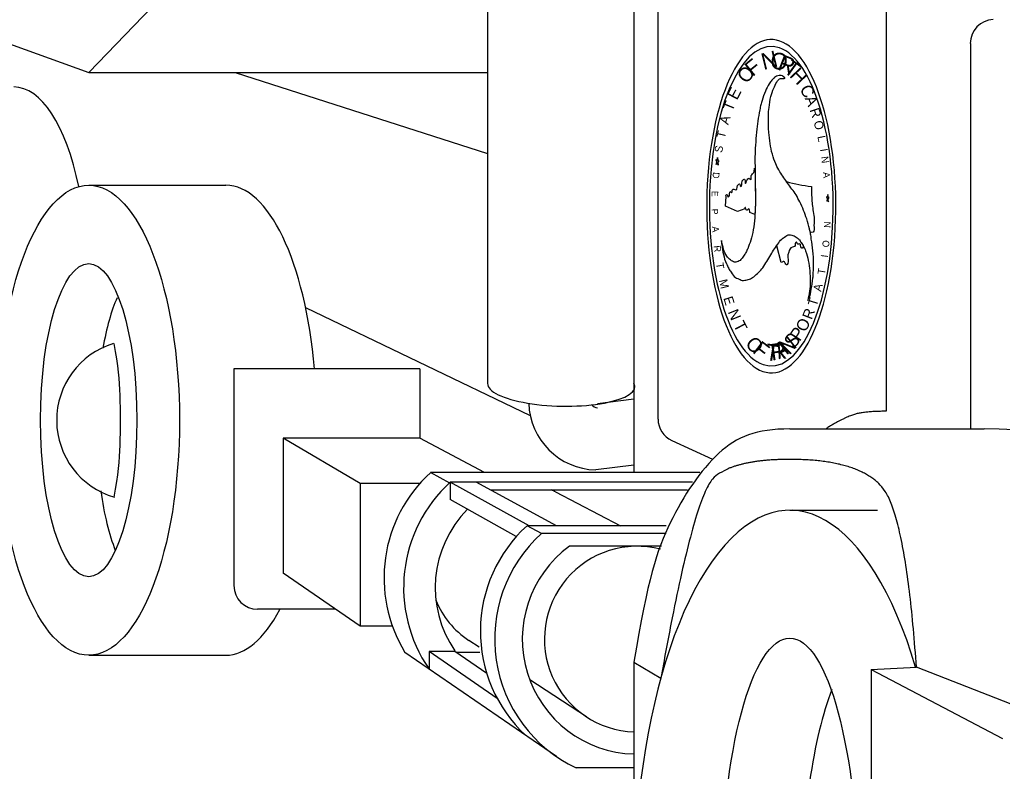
# Model space of a CAD drawing. Extents: x 2141134 to 2191774, y 803576 to 836576.
# Drawn here: x 2150196 to 2150916, y 806166 to 806717 of the extents above; entities that cross this region are included whole.
import ezdxf

# ---------------------------------------------------------------- set-up
doc = ezdxf.new("R2010")
doc.units = 0
doc.layers.add('Exist Road Secondary Type 20 SR Number Label', color=7, linetype='Continuous')

msp = doc.modelspace()

# ---------------------------------------------------------------- linework, layer by layer
at = {"layer": 'Exist Road Secondary Type 20 SR Number Label'}
for p, q in [((2150246.63, 806678.14), (2150510.12, 806951.17)), ((2150538.92, 806898.09), (2150538.92, 806450.48)), ((2150050.42, 806749.28), (2150246.63, 806678.14)), ((2150646.15, 806734.75), (2150646.15, 806385.23)), ((2150663.82, 806424.37), (2150663.82, 806736.48)), ((2150831.04, 806729.27), (2150831.04, 806430.07)), ((2150892.6, 806699.59), (2150892.6, 806417.14)), ((2150246.63, 806678.14), (2150538.92, 806678.14)), ((2150354.03, 806678.14), (2150538.92, 806618.9)), ((2150756.67, 806674.43), (2150756.58, 806674.2)), ((2150756.67, 806674.43), (2150756.58, 806674.2)), ((2150756.67, 806674.43), (2150756.58, 806674.2)), ((2150706.83, 806612.84), (2150706.24, 806614.32)), ((2150706.24, 806614.32), (2150707.07, 806614.04)), ((2150706.83, 806612.84), (2150706.24, 806614.32)), ((2150706.24, 806614.32), (2150707.07, 806614.04)), ((2150706.49, 806610.91), (2150706.83, 806612.84)), ((2150706.49, 806610.91), (2150706.83, 806612.84)), ((2150707.18, 806611.95), (2150706.49, 806610.91)), ((2150707.18, 806611.95), (2150706.49, 806610.91)), ((2150707.07, 806614.04), (2150707.39, 806615.9)), ((2150707.07, 806614.04), (2150707.39, 806615.9)), ((2150707.79, 806610.47), (2150707.18, 806611.95)), ((2150707.79, 806610.47), (2150707.18, 806611.95)), ((2150707.39, 806615.9), (2150707.57, 806613.87)), ((2150707.39, 806615.9), (2150707.57, 806613.87)), ((2150707.57, 806613.87), (2150708.37, 806613.59)), ((2150707.57, 806613.87), (2150708.37, 806613.59)), ((2150708.37, 806613.59), (2150707.64, 806612.56)), ((2150708.37, 806613.59), (2150707.64, 806612.56)), ((2150707.64, 806612.56), (2150707.79, 806610.47)), ((2150707.64, 806612.56), (2150707.79, 806610.47)), ((2150757.86, 806598.39), (2150757.86, 806598.39)), ((2150757.86, 806598.39), (2150757.86, 806598.39)), ((2150246.63, 806595.67), (2150347.17, 806595.67)), ((2150713.12, 806580.24), (2150713.59, 806587.49)), ((2150713.12, 806580.24), (2150713.59, 806587.49)), ((2150787.9, 806586.99), (2150787.1, 806587.26)), ((2150787.1, 806587.26), (2150787.7, 806585.82)), ((2150787.9, 806586.99), (2150787.1, 806587.26)), ((2150787.1, 806587.26), (2150787.7, 806585.82)), ((2150787.7, 806585.82), (2150787.36, 806583.89)), ((2150787.7, 806585.82), (2150787.36, 806583.89)), ((2150787.36, 806583.89), (2150788.05, 806584.89)), ((2150787.36, 806583.89), (2150788.05, 806584.89)), ((2150788.25, 806588.84), (2150787.9, 806586.99)), ((2150788.25, 806588.84), (2150787.9, 806586.99)), ((2150788.05, 806584.89), (2150788.64, 806583.45)), ((2150788.05, 806584.89), (2150788.64, 806583.45)), ((2150788.43, 806586.81), (2150788.25, 806588.84)), ((2150788.43, 806586.81), (2150788.25, 806588.84)), ((2150789.23, 806586.61), (2150788.43, 806586.81)), ((2150789.23, 806586.61), (2150788.43, 806586.81)), ((2150788.51, 806585.54), (2150789.23, 806586.61)), ((2150788.51, 806585.54), (2150789.23, 806586.61)), ((2150788.64, 806583.45), (2150788.51, 806585.54)), ((2150788.64, 806583.45), (2150788.51, 806585.54)), ((2150721.97, 806576.33), (2150713.12, 806580.24)), ((2150721.97, 806576.33), (2150713.12, 806580.24)), ((2150727.27, 806578.45), (2150721.97, 806576.33)), ((2150727.27, 806578.45), (2150721.97, 806576.33)), ((2150734.82, 806574.22), (2150731.12, 806575.6)), ((2150734.82, 806574.22), (2150731.12, 806575.6)), ((2150793.66, 806564.21), (2150793.66, 806564.21)), ((2150793.66, 806564.21), (2150793.66, 806564.21)), ((2150754.12, 806539.02), (2150750.75, 806551.38)), ((2150750.75, 806551.38), (2150750.75, 806551.38)), ((2150754.12, 806539.02), (2150750.75, 806551.38)), ((2150750.75, 806551.38), (2150750.75, 806551.38)), ((2150405.56, 806506.04), (2150570.09, 806427.09)), ((2150353.06, 806461.07), (2150353.06, 806302.38)), ((2150489.33, 806461.07), (2150489.33, 806410.45)), ((2150646.15, 806438.83), (2150619.33, 806435.5)), ((2150445.47, 806377.27), (2150389.03, 806410.45)), ((2150389.03, 806410.45), (2150389.03, 806311.57)), ((2150536.72, 806385.23), (2150489.33, 806410.45)), ((2150760.33, 806417.14), (2150902.72, 806417.14)), ((2150674, 806408.56), (2150703.7, 806395.06)), ((2150646.15, 806390.58), (2150618.14, 806387.1)), ((2150511.23, 806377.48), (2150497.19, 806385.23)), ((2150445.47, 806377.27), (2150445.47, 806272.58)), ((2150569.41, 806346.26), (2150511.58, 806378.13)), ((2150511.58, 806378.13), (2150511.58, 806365.43)), ((2150689, 806378.13), (2150511.58, 806378.13)), ((2150589.36, 806346.26), (2150530.52, 806378.13)), ((2150685.27, 806372.34), (2150541.21, 806372.34)), ((2150588.67, 806371), (2150636.2, 806346.26)), ((2150559.89, 806338.24), (2150511.58, 806365.43)), ((2150760.33, 806357.56), (2150824.5, 806357.56)), ((2150578.3, 806340.47), (2150567.81, 806346.26)), ((2150669.79, 806346.26), (2150567.81, 806346.26)), ((2150666.37, 806331.18), (2150598.89, 806331.18)), ((2150445.47, 806272.58), (2150389.03, 806311.57)), ((2150532.85, 806257.29), (2150525.21, 806262.25)), ((2150589.37, 806177.13), (2150478.33, 806253.46)), ((2150546, 806219.64), (2150496.02, 806254)), ((2150496.02, 806254), (2150496.02, 806241.31)), ((2150538.33, 806237.93), (2150514.96, 806254)), ((2150246.63, 806251.37), (2150347.17, 806251.37)), ((2150646.15, 806246.36), (2150665.85, 806234.58)), ((2150646.15, 806246.36), (2150646.15, 805934.23)), ((2150819.93, 806241.01), (2150853.13, 806242.62)), ((2150819.93, 806241.01), (2150819.93, 806113.39)), ((2150819.93, 806241.01), (2150916.05, 806190.3)), ((2151011.08, 806180.8), (2150853.13, 806242.62)), ((2150611.47, 806206.18), (2150569.86, 806233.23))]:
    msp.add_line(p, q, dxfattribs=at)
for points in [[(2150489.33, 806461.07), (2150353.06, 806461.07)], [(2150489.33, 806410.45), (2150389.03, 806410.45)], [(2150694.33, 806385.23), (2150497.19, 806385.23)], [(2150489.33, 806377.27), (2150445.47, 806377.27)], [(2150669.79, 806340.47), (2150578.3, 806340.47)], [(2150427.47, 806285.01), (2150370.43, 806285.01)], [(2150469.16, 806272.58), (2150445.47, 806272.58)], [(2150514.96, 806254), (2150496.02, 806254)], [(2150533.11, 806253.46), (2150515.74, 806253.46)], [(2150646.15, 806168.82), (2150603.8, 806168.82)]]:
    msp.add_lwpolyline(points, dxfattribs=at)
for centre, radius, start, end in [((2150909.96, 806699.59), 17.37, 92.07945, 180), ((2150281.92, 806423.52), 58.74, 106.95895, 253.78048), ((2150619.46, 806437.55), 50.47, 181.85685, 268.49256), ((2150619.46, 806437.55), 4.91, 212.61184, 268.49256), ((2150681.19, 806424.37), 17.37, 180, 245.54907), ((2150902.72, 806008.17), 408.97, 41.01358, 90), ((2150567.43, 806307.94), 104.43, 132.26282, 211.44584), ((2150581.82, 806300.84), 104.43, 132.26282, 214.75513), ((2150559.56, 806315.1), 63.03, 62.49925, 65.51247), ((2150581.82, 806300.84), 81.31, 135.04479, 214.75513), ((2150638.04, 806268.97), 104.43, 132.26282, 226.90002), ((2150648.53, 806263.18), 104.43, 132.26282, 244.64068), ((2150648.53, 806263.18), 84.19, 126.13067, 268.38157), ((2150648.53, 806263.18), 67.99, 75.44496, 267.99604), ((2150370.43, 806302.38), 17.37, 180, 270), ((2150559.56, 806315.1), 63.03, 201.74287, 236.97488)]:
    msp.add_arc(centre, radius, start, end, dxfattribs=at)
for centre, major_axis, ratio, start_param, end_param in [((2150746.76, 806580.28), (0, 122.07), 0.387649, 4.580113, 7.721705), ((2150746.76, 806580.28), (0, 122.07), 0.387649, 4.580113, 7.721705), ((2150746.76, 806580.28), (0, 116.98), 0.387649, 4.580113, 7.721705), ((2150746.76, 806580.28), (0, 116.98), 0.387649, 4.580113, 7.721705), ((2150191.86, 806528.25), (0, 139.42), 0.387713, 5.208857, 6.283185), ((2150785.93, 807237.89), (0, -643.58), 0.387649, 6.075485, 6.077223), ((2150785.93, 807237.89), (0, -643.58), 0.387649, 6.075485, 6.077223), ((2150785.93, 807237.89), (0, -643.58), 0.387649, 6.170414, 6.243823), ((2150785.93, 807237.89), (0, -643.58), 0.387649, 6.170414, 6.243823), ((2150347.17, 806423.52), (0, 172.15), 0.386478, 4.932222, 6.283185), ((2150746.76, 806580.28), (0, -122.06), 0.387649, 4.580113, 7.721705), ((2150746.76, 806580.28), (0, -122.06), 0.387649, 4.580113, 7.721705), ((2150746.76, 806580.28), (0, -116.98), 0.387649, 4.580113, 7.721705), ((2150746.76, 806580.28), (0, -116.98), 0.387649, 4.580113, 7.721705), ((2150287.63, 806419.18), (0, 114.7), 0.307656, 0.60872, 1.048981), ((2150592.87, 806449.26), (-53.95, 1.21), 0.285874, 6.283185, 9.588173), ((2150760.33, 806077.13), (0, 280.43), 0.407167, 5.343461, 11.004346), ((2150287.63, 806419.18), (0, 114.7), 0.307656, 1.996276, 2.486784), ((2150347.17, 806423.52), (0, 172.15), 0.386478, 3.141593, 3.775764), ((2150819.17, 806071.08), (0, -186.85), 0.26845, 3.733099, 4.225572)]:
    msp.add_ellipse(centre, major_axis=major_axis, ratio=ratio, start_param=start_param, end_param=end_param, dxfattribs=at)
for centre, major_axis, ratio in [((2150246.63, 806423.52), (0, 172.15), 0.386478), ((2150246.63, 806423.52), (0, 114.7), 0.307656), ((2150760.33, 806077.13), (0, -186.85), 0.26845)]:
    msp.add_ellipse(centre, major_axis=major_axis, ratio=ratio, dxfattribs=at)
for points in [[(2150756.58, 806674.2), (2150755.56, 806675.28), (2150752.43, 806676.03), (2150749.12, 806674.5), (2150748.82, 806674.2), (2150747.13, 806672.59), (2150745.28, 806669.94), (2150742.41, 806664.61), (2150740.07, 806657.64), (2150739.13, 806654.64), (2150738.35, 806650.82), (2150736.87, 806642.65), (2150735.9, 806634.58), (2150735.19, 806625.01), (2150734.81, 806616.52), (2150734.91, 806607.69), (2150735.04, 806598.78), (2150735.09, 806590.15), (2150735.1, 806581.28), (2150734.67, 806572.63), (2150734.62, 806571.88), (2150733.54, 806562.87), (2150731.68, 806555.3), (2150729.47, 806549.16), (2150728.21, 806546.41), (2150726.48, 806543.8), (2150725.49, 806542.27), (2150723.22, 806540.21), (2150719.91, 806539.37), (2150716.79, 806540.92), (2150714.11, 806543.7), (2150711.87, 806548.59), (2150710.23, 806555.06)], [(2150756.58, 806674.2), (2150755.56, 806675.28), (2150752.43, 806676.03), (2150749.12, 806674.5), (2150748.82, 806674.2), (2150747.13, 806672.59), (2150745.28, 806669.94), (2150742.41, 806664.61), (2150740.07, 806657.64), (2150739.13, 806654.64), (2150738.35, 806650.82), (2150736.87, 806642.65), (2150735.9, 806634.58), (2150735.19, 806625.01), (2150734.81, 806616.52), (2150734.91, 806607.69), (2150735.04, 806598.78), (2150735.09, 806590.15), (2150735.1, 806581.28), (2150734.67, 806572.63), (2150734.62, 806571.88), (2150733.54, 806562.87), (2150731.68, 806555.3), (2150729.47, 806549.16), (2150728.21, 806546.41), (2150726.48, 806543.8), (2150725.49, 806542.27), (2150723.22, 806540.21), (2150719.91, 806539.37), (2150716.79, 806540.92), (2150714.11, 806543.7), (2150711.87, 806548.59), (2150710.23, 806555.06)], [(2150773.43, 806511.15), (2150774.26, 806512.83), (2150776.1, 806519.46), (2150777.24, 806527.61), (2150777.33, 806528.42), (2150777.59, 806533.04), (2150777.63, 806538.54), (2150777.31, 806547.59), (2150776.1, 806556.25), (2150775.6, 806559.9), (2150774.68, 806563.6), (2150772.69, 806570.97), (2150770.47, 806577.17), (2150767.6, 806583.48), (2150764.93, 806588.52), (2150761.92, 806592.84), (2150758.87, 806596.95), (2150755.98, 806601.12), (2150752.94, 806605.59), (2150750.28, 806610.85), (2150750.07, 806611.4), (2150747.54, 806618.32), (2150745.94, 806626.28), (2150744.96, 806634.24), (2150744.72, 806638.38), (2150744.71, 806643.6), (2150744.65, 806646.61), (2150745.14, 806652.65), (2150746.5, 806660.54), (2150748.56, 806666.66), (2150750.85, 806671.24), (2150753.63, 806673.79), (2150756.58, 806674.2), (2150756.67, 806674.43)], [(2150773.43, 806511.15), (2150774.26, 806512.83), (2150776.1, 806519.46), (2150777.24, 806527.61), (2150777.33, 806528.42), (2150777.59, 806533.04), (2150777.63, 806538.54), (2150777.31, 806547.59), (2150776.1, 806556.25), (2150775.6, 806559.9), (2150774.68, 806563.6), (2150772.69, 806570.97), (2150770.47, 806577.17), (2150767.6, 806583.48), (2150764.93, 806588.52), (2150761.92, 806592.84), (2150758.87, 806596.95), (2150755.98, 806601.12), (2150752.94, 806605.59), (2150750.28, 806610.85), (2150750.07, 806611.4), (2150747.54, 806618.32), (2150745.94, 806626.28), (2150744.96, 806634.24), (2150744.72, 806638.38), (2150744.71, 806643.6), (2150744.65, 806646.61), (2150745.14, 806652.65), (2150746.5, 806660.54), (2150748.56, 806666.66), (2150750.85, 806671.24), (2150753.63, 806673.79), (2150756.58, 806674.2), (2150756.67, 806674.43)], [(2150713.59, 806587.49), (2150713.53, 806588.21), (2150714.04, 806588.83), (2150715.29, 806586.98), (2150716.03, 806588.22), (2150716.08, 806589.7), (2150716.69, 806590.99), (2150717.57, 806590.22), (2150718.52, 806592.62), (2150719.3, 806592.83), (2150720.88, 806592.29), (2150723.01, 806596.52), (2150723.82, 806596.54), (2150723.95, 806595.18), (2150724.42, 806594.76), (2150725.43, 806598.5), (2150725.67, 806599), (2150727.22, 806600), (2150727.58, 806599.15), (2150727.6, 806597.32), (2150727.79, 806596.89), (2150728.32, 806597.62), (2150729.08, 806599.55), (2150730.38, 806600.75), (2150731.73, 806599.84), (2150732.12, 806602.67), (2150733.87, 806604.91), (2150734.29, 806606.48), (2150734.47, 806608.18)], [(2150713.59, 806587.49), (2150713.53, 806588.21), (2150714.04, 806588.83), (2150715.29, 806586.98), (2150716.03, 806588.22), (2150716.08, 806589.7), (2150716.69, 806590.99), (2150717.57, 806590.22), (2150718.52, 806592.62), (2150719.3, 806592.83), (2150720.88, 806592.29), (2150723.01, 806596.52), (2150723.82, 806596.54), (2150723.95, 806595.18), (2150724.42, 806594.76), (2150725.43, 806598.5), (2150725.67, 806599), (2150727.22, 806600), (2150727.58, 806599.15), (2150727.6, 806597.32), (2150727.79, 806596.89), (2150728.32, 806597.62), (2150729.08, 806599.55), (2150730.38, 806600.75), (2150731.73, 806599.84), (2150732.12, 806602.67), (2150733.87, 806604.91), (2150734.29, 806606.48), (2150734.47, 806608.18)], [(2150734.9, 806607.91), (2150734.91, 806607.69), (2150735.04, 806598.78), (2150735.09, 806590.15), (2150735.1, 806581.28), (2150734.81, 806574.22)], [(2150734.9, 806607.91), (2150734.91, 806607.69), (2150735.04, 806598.78), (2150735.09, 806590.15), (2150735.1, 806581.28), (2150734.81, 806574.22)], [(2150775.31, 806561.31), (2150774.68, 806563.6), (2150772.69, 806570.97), (2150770.47, 806577.17), (2150767.6, 806583.48), (2150764.93, 806588.52), (2150761.92, 806592.84), (2150758.87, 806596.95), (2150757.86, 806598.39)], [(2150775.31, 806561.31), (2150774.68, 806563.6), (2150772.69, 806570.97), (2150770.47, 806577.17), (2150767.6, 806583.48), (2150764.93, 806588.52), (2150761.92, 806592.84), (2150758.87, 806596.95), (2150757.86, 806598.39)], [(2150776.11, 806594.79), (2150776.36, 806586.5), (2150777.51, 806576.43), (2150778.3, 806570.87), (2150778.04, 806566.39), (2150777.36, 806561.19), (2150775.33, 806561.34)], [(2150776.11, 806594.79), (2150776.36, 806586.5), (2150777.51, 806576.43), (2150778.3, 806570.87), (2150778.04, 806566.39), (2150777.36, 806561.19), (2150775.33, 806561.34)], [(2150731.12, 806575.6), (2150730.85, 806577.48), (2150730.15, 806578.27), (2150729.11, 806577.27), (2150728.38, 806577.64), (2150727.65, 806579.42), (2150727.27, 806578.45)], [(2150731.12, 806575.6), (2150730.85, 806577.48), (2150730.15, 806578.27), (2150729.11, 806577.27), (2150728.38, 806577.64), (2150727.65, 806579.42), (2150727.27, 806578.45)], [(2150710.23, 806555.06), (2150710.43, 806552.22), (2150711.73, 806544.84), (2150713.88, 806538.19), (2150714.12, 806537.74), (2150715.54, 806534.67), (2150717.35, 806531.93), (2150720.57, 806528.12), (2150724.06, 806526.49), (2150725.53, 806525.8), (2150727.28, 806526), (2150730.69, 806526.8), (2150733.87, 806528.59), (2150737.46, 806531.85), (2150740.47, 806535.24), (2150743.42, 806539.88), (2150746.33, 806544.68), (2150749.22, 806549.06), (2150752.2, 806553.47), (2150755.31, 806556.89), (2150755.64, 806557.11), (2150759.21, 806559.24), (2150762.64, 806558.87), (2150765.77, 806557.06), (2150767.38, 806555.6), (2150769.07, 806552.94), (2150770.14, 806551.58), (2150771.93, 806547.5), (2150773.85, 806540.53), (2150774.89, 806532.87), (2150775.3, 806525.4), (2150774.78, 806517.95), (2150773.43, 806511.15)], [(2150710.23, 806555.06), (2150710.43, 806552.22), (2150711.73, 806544.84), (2150713.88, 806538.19), (2150714.12, 806537.74), (2150715.54, 806534.67), (2150717.35, 806531.93), (2150720.57, 806528.12), (2150724.06, 806526.49), (2150725.53, 806525.8), (2150727.28, 806526), (2150730.69, 806526.8), (2150733.87, 806528.59), (2150737.46, 806531.85), (2150740.47, 806535.24), (2150743.42, 806539.88), (2150746.33, 806544.68), (2150749.22, 806549.06), (2150752.2, 806553.47), (2150755.31, 806556.89), (2150755.64, 806557.11), (2150759.21, 806559.24), (2150762.64, 806558.87), (2150765.77, 806557.06), (2150767.38, 806555.6), (2150769.07, 806552.94), (2150770.14, 806551.58), (2150771.93, 806547.5), (2150773.85, 806540.53), (2150774.89, 806532.87), (2150775.3, 806525.4), (2150774.78, 806517.95), (2150773.43, 806511.15)], [(2150750.75, 806551.38), (2150752.2, 806553.47), (2150755.31, 806556.89), (2150755.64, 806557.11), (2150759.21, 806559.24), (2150762.64, 806558.87), (2150765.77, 806557.06), (2150767.38, 806555.6), (2150769.07, 806552.94), (2150770.06, 806551.65)], [(2150750.75, 806551.38), (2150752.2, 806553.47), (2150755.31, 806556.89), (2150755.64, 806557.11), (2150759.21, 806559.24), (2150762.64, 806558.87), (2150765.77, 806557.06), (2150767.38, 806555.6), (2150769.07, 806552.94), (2150770.06, 806551.65)], [(2150770.05, 806551.62), (2150769.51, 806549.65), (2150768.79, 806549.75), (2150767.68, 806552.72), (2150766.13, 806552.45), (2150765.49, 806553.73), (2150765.03, 806553.92), (2150763.75, 806550.75), (2150762.2, 806550.4), (2150759.53, 806546.61), (2150758.89, 806544.09), (2150758.77, 806538.22), (2150758.12, 806537.28), (2150757.41, 806537.82), (2150755.98, 806539.84), (2150754.12, 806539.02)], [(2150770.05, 806551.62), (2150769.51, 806549.65), (2150768.79, 806549.75), (2150767.68, 806552.72), (2150766.13, 806552.45), (2150765.49, 806553.73), (2150765.03, 806553.92), (2150763.75, 806550.75), (2150762.2, 806550.4), (2150759.53, 806546.61), (2150758.89, 806544.09), (2150758.77, 806538.22), (2150758.12, 806537.28), (2150757.41, 806537.82), (2150755.98, 806539.84), (2150754.12, 806539.02)]]:
    msp.add_spline(points, degree=3, dxfattribs=at)
for points, degree in [([(2150265.32, 806367.15), (2150268.35, 806383.91), (2150270.08, 806403.67), (2150270.08, 806443.34), (2150268.35, 806463.07), (2150265.33, 806479.81)], 3), ([(2150265.32, 806367.15), (2150268.35, 806383.91), (2150270.08, 806403.67), (2150270.08, 806443.34), (2150268.35, 806463.07), (2150265.33, 806479.81)], 3), ([(2150831.04, 806430.07), (2150816.69, 806430.07), (2150801.18, 806426.22), (2150786.98, 806417.44)], 2), ([(2150831.04, 806430.07), (2150816.69, 806430.07), (2150801.18, 806426.22), (2150786.98, 806417.44)], 2), ([(2150760.33, 806417.14), (2150735.72, 806417.14), (2150707.67, 806405.79), (2150669.78, 806349.63), (2150656.13, 806307.25), (2150646.15, 806246.36)], 3), ([(2150760.33, 806417.14), (2150735.72, 806417.14), (2150707.67, 806405.79), (2150669.78, 806349.63), (2150656.13, 806307.25), (2150646.15, 806246.36)], 3), ([(2150760.33, 806394.82), (2150720.67, 806394.82), (2150689.85, 806369.34), (2150665.85, 806234.58)], 2), ([(2150760.33, 806394.82), (2150720.67, 806394.82), (2150689.85, 806369.34), (2150665.85, 806234.58)], 2), ([(2150853.13, 806242.62), (2150845.26, 806355.47), (2150809.62, 806394.82), (2150760.33, 806394.82)], 2), ([(2150853.13, 806242.62), (2150845.26, 806355.47), (2150809.62, 806394.82), (2150760.33, 806394.82)], 2)]:
    msp.add_open_spline(points, degree=degree, dxfattribs=at)

# ---------------------------------------------------------------- texts
for s, height, rotation, p in [('N', 12.07, 13.71613, (2150741.06, 806680.04)), ('O', 12.19, 354.61379, (2150745.65, 806681.09)), ('R', 11.91, 338.45159, (2150750.64, 806680.62)), ('F', 11.19, 39.10968, (2150733.1, 806674.78)), ('T', 11.41, 324.6913, (2150755.1, 806678.87)), ('O', 10.34, 49.79583, (2150728.56, 806669.48)), ('H', 10.58, 313.19088, (2150759.55, 806675.63)), ('E', 8.72, 62.41801, (2150721.6, 806657.48)), ('C', 8.96, 299.16907, (2150767.27, 806666.19)), ('T', 7.81, 67.9156, (2150718.25, 806649.29)), ('A', 8, 293.09177, (2150771.13, 806659.21)), ('R', 7.23, 288.84313, (2150774.71, 806650.82)), ('A', 7.02, 72.4252, (2150715.16, 806639.55)), ('O', 6.48, 284.77998, (2150777.68, 806642.07)), ('T', 6.29, 76.28214, (2150712.65, 806629.57)), ('L', 5.89, 281.64933, (2150780.51, 806631.35)), ('S', 5.72, 79.37561, (2150710.68, 806619.15)), ('I', 5.6, 279.79982, (2150782.35, 806621.96)), ('N', 5.23, 277.31258, (2150783.25, 806616.5)), ('D', 4.86, 266.19873, (2150704.03, 806605.37)), ('A', 4.9, 274.26298, (2150784.68, 806605.14)), ('E', 4.72, 268.66591, (2150703.16, 806591.58)), ('P', 4.74, 271.58949, (2150702.95, 806578.37)), ('A', 4.89, 274.18407, (2150703.31, 806565.4)), ('N', 4.76, 87.91284, (2150790.2, 806564.37)), ('O', 4.94, 85.04013, (2150789.01, 806550)), ('R', 5.2, 277.07589, (2150704.41, 806551.26)), ('I', 5.21, 82.92463, (2150788.11, 806542.53)), ('T', 5.62, 279.97602, (2150706.04, 806538.51)), ('T', 5.54, 80.47534, (2150786.02, 806529.89)), ('M', 6.2, 283.43437, (2150708.33, 806526.01)), ('A', 6.13, 77.14306, (2150783.24, 806517.38)), ('E', 6.96, 287.49085, (2150711.56, 806512.97)), ('T', 6.9, 72.81905, (2150779.97, 806506.46)), ('N', 7.81, 291.92669, (2150714.81, 806502.87)), ('R', 7.64, 69.02902, (2150776.34, 806496.75)), ('T', 8.67, 297.15618, (2150718.69, 806493.44)), ('O', 8.56, 63.72172, (2150771.88, 806487.59)), ('P', 9.43, 57.62566, (2150767.59, 806480.7)), ('O', 10.43, 311.34666, (2150727.11, 806479.2)), ('N', 11.17, 38.33343, (2150757.77, 806470.82)), ('S', 10.33, 49.2884, (2150762.85, 806475.11)), ('F', 11.24, 322.4218, (2150732.36, 806473.45)), ('T', 12.08, 350.52834, (2150741.76, 806467.89)), ('R', 12.14, 8.34952, (2150747.1, 806467.15)), ('A', 11.78, 24.47975, (2150752.3, 806468.11))]:
    msp.add_text(s, height=height, rotation=rotation, dxfattribs=at).set_placement(p)

doc.saveas('drawing.dxf')
